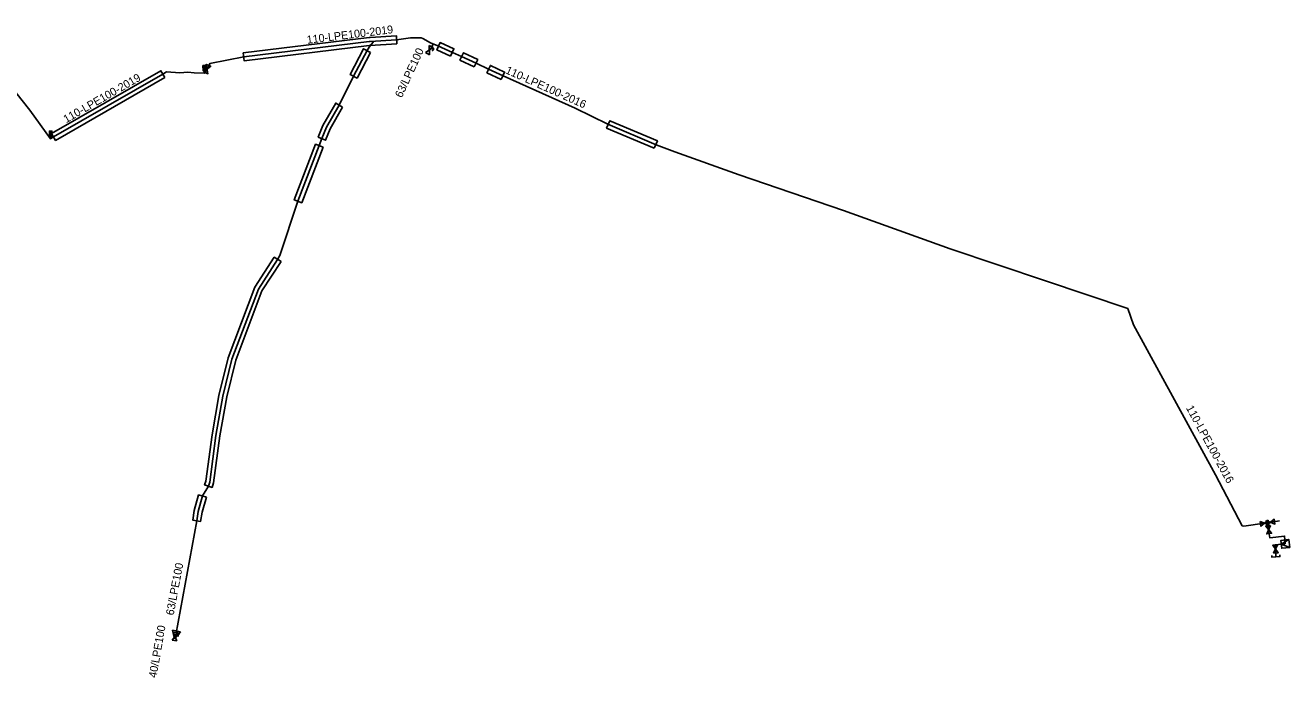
# Model space of a CAD drawing. Extents: x -787723 to -786204, y -1153846 to -1152384.
# Drawn here: x -787579.9 to -787422, y -1153846.2 to -1153764.7 of the extents above; entities that cross this region are included whole.
import ezdxf

# ---------------------------------------------------------------- set-up
doc = ezdxf.new("R2010")
doc.units = 0
for name, color, linetype in [('Vrstva 1', 7, 'Continuous'), ('Vrstva 21', 7, 'Continuous'), ('Vrstva 22', 7, 'Continuous'), ('Vrstva 24', 7, 'Continuous'), ('Vrstva 27', 7, 'Continuous'), ('Vrstva 29', 7, 'Continuous'), ('Vrstva 31', 7, 'Continuous'), ('Vrstva 32', 7, 'Continuous'), ('Vrstva 36', 7, 'Continuous')]:
    doc.layers.add(name, color=color, linetype=linetype)

# ---------------------------------------------------------------- blocks, each defined once
blk = doc.blocks.new('DEC091')
at = {"layer": 'Vrstva 1'}
for points in [[(-0.5, 0.5), (0.5, 0), (-0.5, -0.5)], [(-0.5, 0.5), (0.5, 0.5), (0.5, -0.5), (-0.5, -0.5), (-0.5, 0.5)]]:
    blk.add_lwpolyline(points, dxfattribs=at)
blk = doc.blocks.new('DEC063-SN')
at = {"layer": 'Vrstva 1'}
for p, q in [((-0.5, -0.3), (0.5, 0.3)), ((0.5, -0.3), (-0.5, 0.3)), ((-0.5, 0.3), (-0.5, -0.3)), ((0.5, 0.3), (0.5, -0.3)), ((0.126, -0.318), (0.126, -0.458)), ((0.126, -0.384), (0.206, -0.384)), ((0.206, -0.458), (0.206, -0.318)), ((0.366, -0.458), (0.366, -0.318))]:
    blk.add_line(p, q, dxfattribs=at)
for points in [[(0.246, -0.318), (0.246, -0.418), (0.252, -0.438), (0.264, -0.451), (0.281, -0.458), (0.292, -0.458), (0.309, -0.451), (0.321, -0.438), (0.326, -0.418), (0.326, -0.318)], [(0.366, -0.318), (0.418, -0.318), (0.435, -0.325), (0.441, -0.331), (0.446, -0.344), (0.446, -0.364), (0.441, -0.378), (0.435, -0.384), (0.418, -0.391), (0.366, -0.391)]]:
    blk.add_lwpolyline(points, dxfattribs=at)
blk = doc.blocks.new('DEC129')
at = {"layer": 'Vrstva 1'}
blk.add_line((0, 1), (0, 0), dxfattribs=at)
blk.add_lwpolyline([(-0.15, 1), (0.15, 1), (0.15, 0.3), (-0.15, 0.3), (-0.15, 1)], dxfattribs=at)
blk = doc.blocks.new('DEC122-SN')
at = {"layer": 'Vrstva 1'}
for p, q in [((-0.5, 0.5), (0.5, 0)), ((-0.5, -0.5), (-0.5, 0.5)), ((0.5, 0), (-0.5, -0.5))]:
    blk.add_line(p, q, dxfattribs=at)
blk = doc.blocks.new('DEC130')
at = {"layer": 'Vrstva 1'}
blk.add_lwpolyline([(0.2, 0.5), (0, 0.5), (0, -0.5), (0.2, -0.5)], dxfattribs=at)
blk = doc.blocks.new('DEC124')
at = {"layer": 'Vrstva 1'}
blk.add_lwpolyline([(-0.5, 0.3), (0.5, -0.3), (0.5, 0.3), (-0.5, -0.3), (-0.5, 0.3)], dxfattribs=at)

msp = doc.modelspace()

# ---------------------------------------------------------------- linework, layer by layer
at = {"layer": 'Vrstva 21'}
for points in [[(-787530.27, -1153766.39), (-787530.5, -1153766.31), (-787531.83, -1153766.3), (-787533.56, -1153766.54), (-787536.88, -1153766.75), (-787536.98, -1153766.74), (-787552.66, -1153768.69), (-787556.91, -1153769.51), (-787557.24, -1153770.2)], [(-787427.71, -1153827.26), (-787427.92, -1153827.23), (-787431.26, -1153820.86), (-787441.5, -1153802.13), (-787442.21, -1153800.11), (-787452.5, -1153796.64), (-787464.39, -1153792.64), (-787477.71, -1153787.88), (-787490.74, -1153783.39), (-787498.81, -1153780.55), (-787501.13, -1153779.65), (-787507.15, -1153777.1), (-787511.24, -1153775.09), (-787520.24, -1153771.05), (-787522.07, -1153770.2), (-787523.62, -1153769.47), (-787525.44, -1153768.61), (-787526.59, -1153768.12), (-787528.42, -1153767.31), (-787529.31, -1153766.92), (-787530.27, -1153766.39)], [(-787557.24, -1153770.2), (-787557.54, -1153770.72), (-787558.83, -1153770.67), (-787559.63, -1153770.58), (-787560.63, -1153770.66), (-787562.29, -1153770.53), (-787562.75, -1153770.83), (-787576.41, -1153778.68), (-787576.79, -1153778.93), (-787579.39, -1153775.34), (-787584.52, -1153768.93)], [(-787424.37, -1153826.79), (-787424.71, -1153826.84)], [(-787423.25, -1153826.62), (-787423.76, -1153826.7), (-787424.37, -1153826.79)], [(-787425.12, -1153826.91), (-787427.71, -1153827.26)], [(-787424.71, -1153826.84), (-787425.12, -1153826.91)], [(-787424.71, -1153826.84), (-787424.61, -1153827.72)], [(-787424.61, -1153827.72), (-787424.48, -1153828.72), (-787422.62, -1153828.51), (-787422.53, -1153829.49)], [(-787422.53, -1153829.49), (-787423.81, -1153829.62), (-787423.76, -1153830.13)], [(-787423.76, -1153830.13), (-787423.7, -1153831.12)]]:
    msp.add_lwpolyline(points, dxfattribs=at)
at = {"layer": 'Vrstva 29'}
for points in [[(-787533.53, -1153767.04), (-787536.89, -1153767.25), (-787536.97, -1153767.24), (-787552.6, -1153769.19), (-787552.72, -1153768.19), (-787536.99, -1153766.24), (-787536.87, -1153766.25), (-787533.59, -1153766.04)], [(-787536.8, -1153768.13), (-787538.49, -1153771.32), (-787539.37, -1153770.86), (-787537.68, -1153767.67)], [(-787526.81, -1153768.57), (-787528.52, -1153767.81), (-787528.12, -1153766.9), (-787526.4, -1153767.66)], [(-787523.85, -1153769.91), (-787525.65, -1153769.07), (-787525.22, -1153768.16), (-787523.43, -1153769.01)], [(-787520.48, -1153771.49), (-787522.27, -1153770.66), (-787521.84, -1153769.75), (-787520.06, -1153770.58)], [(-787562.5, -1153771.26), (-787576.16, -1153779.11), (-787576.66, -1153778.25), (-787563, -1153770.4)], [(-787540.3, -1153774.95), (-787541.87, -1153777.68), (-787542.43, -1153779.08), (-787543.35, -1153778.7), (-787542.77, -1153777.24), (-787541.16, -1153774.45)], [(-787501.37, -1153780.09), (-787507.32, -1153777.57), (-787506.93, -1153776.65), (-787500.98, -1153779.17)], [(-787542.75, -1153779.94), (-787545.41, -1153786.89), (-787546.35, -1153786.53), (-787543.69, -1153779.58)], [(-787548, -1153794.24), (-787550.38, -1153797.9), (-787553.65, -1153806.56), (-787554.79, -1153811.15), (-787555.64, -1153816.02), (-787556.42, -1153821.88), (-787556.61, -1153822.44), (-787557.55, -1153822.12), (-787557.4, -1153821.66), (-787556.62, -1153815.86), (-787555.77, -1153810.95), (-787554.61, -1153806.26), (-787551.28, -1153797.44), (-787548.84, -1153793.7)], [(-787557.33, -1153823.64), (-787557.86, -1153825.55), (-787558.04, -1153826.68), (-787559.02, -1153826.52), (-787558.84, -1153825.33), (-787558.29, -1153823.38)]]:
    msp.add_lwpolyline(points, close=True, dxfattribs=at)
at = {"layer": 'Vrstva 31'}
for points in [[(-787536.41, -1153766.72), (-787536.98, -1153767.45), (-787536.99, -1153767.48)], [(-787536.99, -1153767.48), (-787537.24, -1153767.9), (-787538.93, -1153771.09), (-787540.73, -1153774.7), (-787542.32, -1153777.46), (-787542.89, -1153778.89), (-787543.22, -1153779.76), (-787545.88, -1153786.71), (-787548.15, -1153793.49), (-787548.42, -1153793.97), (-787550.83, -1153797.67), (-787554.13, -1153806.41), (-787555.28, -1153811.05), (-787556.13, -1153815.94), (-787556.91, -1153821.77), (-787557.08, -1153822.28), (-787557.81, -1153823.51), (-787558.35, -1153825.44), (-787558.53, -1153826.6), (-787561.16, -1153840.84)], [(-787528.99, -1153767.06), (-787529.28, -1153767.69), (-787529.47, -1153767.82)], [(-787561.16, -1153840.84), (-787561.17, -1153840.86), (-787561.24, -1153841.06)]]:
    msp.add_lwpolyline(points, dxfattribs=at)

# ---------------------------------------------------------------- block references
at = {"layer": 'Vrstva 22'}
for name, p, rotation in [('DEC124', (-787557.24, -1153770.2), 68.68493456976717), ('DEC124', (-787425.12, -1153826.91), 8.539676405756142), ('DEC124', (-787424.37, -1153826.79), 7.970206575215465), ('DEC124', (-787424.61, -1153827.72), -82.00206993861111), ('DEC124', (-787423.76, -1153830.13), 95.01934327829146), ('DEC130', (-787423.7, -1153831.12), 94.83041990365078)]:
    msp.add_blockref(name, p, dxfattribs=dict(at, rotation=rotation))
at = {"layer": 'Vrstva 24'}
for p, rotation in [((-787557.54, -1153770.72), 5.667645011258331), ((-787576.79, -1153778.93), -1.4339022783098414)]:
    msp.add_blockref('DEC129', p, dxfattribs=dict(at, rotation=rotation))
at = {"layer": 'Vrstva 27', "rotation": -173.4236206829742}
msp.add_blockref('DEC091', (-787422.53, -1153829.49), dxfattribs=at)
at = {"layer": 'Vrstva 32'}
for p, rotation in [((-787529.47, -1153767.82), 62.9965305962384), ((-787561.24, -1153841.06), 83.45858541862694)]:
    msp.add_blockref('DEC063-SN', p, dxfattribs=dict(at, rotation=rotation))
at = {"layer": 'Vrstva 36', "rotation": -103.29276994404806}
msp.add_blockref('DEC122-SN', (-787561.18, -1153840.86), dxfattribs=at)

# ---------------------------------------------------------------- texts
at = {"layer": 'Vrstva 21'}
for s, rotation, p in [('110-LPE100-2019', 7.089, (-787544.72, -1153767.05)), ('110-LPE100-2016', 335.825, (-787520.05, -1153770.69)), ('110-LPE100-2019', 29.885, (-787574.84, -1153776.97)), ('110-LPE100-2016', 298.655, (-787434.97, -1153812.51))]:
    msp.add_text(s, height=1, rotation=rotation, dxfattribs=at).set_placement(p)
at = {"layer": 'Vrstva 31'}
for s, rotation, p in [('63/LPE100', 65.093, (-787532.91, -1153773.86)), ('63/LPE100', 79.365, (-787561.42, -1153838.47)), ('40/LPE100', 79.983, (-787563.57, -1153846.27))]:
    msp.add_text(s, height=1, rotation=rotation, dxfattribs=at).set_placement(p)

doc.saveas('drawing.dxf')
